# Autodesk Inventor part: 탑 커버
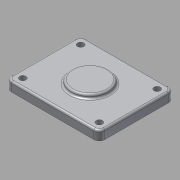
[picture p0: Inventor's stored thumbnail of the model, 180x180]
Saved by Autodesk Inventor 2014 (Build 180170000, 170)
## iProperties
Created: 2017-05
Part Number: 탑 커버
Material: 알루미늄 6061
Document SubType Name: Modeling
Designer: mduedu
Density: 1 g/cm^3
Appearance: 알루미늄 - 평지
Author: mduedu
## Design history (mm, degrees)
sketch "스케치1"
  geometry: L1 (25, 20)-(-25, 20); L2 (-25, 20)-(-25, -20); L3 (-25, -20)-(25, -20); L4 (25, -20)-(25, 20); L5 (25, 20)-(-25, -20); L6 (-25, 20)-(25, -20); 1 further point
  constraints: 12 end point, 2 midpoint, 2 parallel, 1 horizontal, 1 perpendicular
  dimensions: "d0" = 50 distance of L3.end L2.end; "d1" = 40 distance of L2.end L1.end
extrude "돌출1" new body sketch "스케치1" distance "d2" = 5; taper "d3" = 0 deg
fillet "모깎기1" dims "d4" = 3
sketch "스케치2"
  geometry: C1 r 10 at (0, 0); 1 further point
  constraints: 1 centre point, 1 coincident
  dimensions: "d5" = 20 diameter of C1
extrude "돌출2" join sketch "스케치2" distance "d6" = 2; taper "d7" = 0 deg
sketch "스케치3"
  geometry: L1 (-16, -11)-(16, -11); L2 (16, -11)-(16, 11); L3 (16, 11)-(-16, 11); L4 (-16, 11)-(-16, -11); L5 (-16, -11)-(16, 11); L6 (16, -11)-(-16, 11); 1 further point
  constraints: 12 end point, 2 midpoint, 2 parallel, 1 horizontal, 1 perpendicular
  dimensions: "d8" = 32 distance of L3.end L2.end; "d9" = 22 distance of L2.end L1.end
extrude "돌출3" join sketch "스케치3" distance "d10" = 3; taper "d11" = 0 deg
fillet "모깎기2" dims "d12" = 3
sketch "스케치4"
  geometry: L1 (-13, -11)-(13, -11) reference; L2 (16, -8)-(16, 8) reference; L3 (13, 11)-(-13, 11) reference; L4 (-16, 8)-(-16, -8) reference; L5 (-13, 9)-(13, 9); L6 (14, 8)-(14, -8); L7 (13, -9)-(-13, -9); L8 (-14, -8)-(-14, 8); A1 r 3 centre (-13, -8) between (-16, -8) and (-13, -11) reference; A2 r 3 centre (13, -8) between (13, -11) and (16, -8) reference; A3 r 3 centre (13, 8) between (16, 8) and (13, 11) reference; A4 r 3 centre (-13, 8) between (-13, 11) and (-16, 8) reference; A5 r 1 centre (13, 8) between (14, 8) and (13, 9); A6 r 1 centre (13, -8) between (13, -9) and (14, -8); A7 r 1 centre (-13, -8) between (-14, -8) and (-13, -9); A8 r 1 centre (-13, 8) between (-13, 9) and (-14, 8); 1 further point
  constraints: 8 end point, 8 point on circle, 4 centre point, 7 other
  dimensions: "d13" = 2 distance between parallel lines of L5 L3
extrude "돌출4" cut sketch "스케치4" stored distance "d14" = 2; taper "d15" = 0 deg
chamfer "모따기1" distance "d16" = 1; stored, may be unused: second distance "d17" = 2, angle "d18" = 45 deg
fillet "모깎기3" dims "d19" = 1
fillet "모깎기4" dims "d20" = 1
fillet "모깎기5" dims "d21" = 1
sketch "스케치5"
  geometry: L1 (-20.5, -15.5)-(20.5, -15.5); L2 (20.5, -15.5)-(20.5, 15.5); L3 (20.5, 15.5)-(-20.5, 15.5); L4 (-20.5, 15.5)-(-20.5, -15.5); L5 (-20.5, -15.5)-(20.5, 15.5); L6 (20.5, -15.5)-(-20.5, 15.5); L7 (22, 20)-(-22, 20) reference; L8 (25, -17)-(25, 17) reference; 5 further points
  constraints: 12 end point, 4 coincident, 2 midpoint, 2 parallel, 1 horizontal, 1 perpendicular
  dimensions: "d22" = 4.5 distance between parallel lines of L3 L7; "d23" = 4.5 distance between parallel lines of L2 L8
sketch "스케치6"
  geometry: 4 further points
  constraints: 4 other
hole "구멍1" sketch "스케치6" at (-20.5, 15.5), (20.5, 15.5), (20.5, -15.5), (-20.5, -15.5) diameter "d24" = 3.4; stored, may be unused: countersink angle "d28" = 90 deg, drill point angle "d30" = 0 deg; dims "d25" = 6, "d26" = 4, "d27" = 2, "d29" = 8
node "솔리드1"
node "투영된 루프1"
